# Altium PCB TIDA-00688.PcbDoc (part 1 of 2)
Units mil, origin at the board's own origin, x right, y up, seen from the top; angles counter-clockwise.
Board outline 1000 x 2450.32 mil, 4 copper layers (Top Layer, Signal Layer 1, Signal Layer 2, Bottom Layer), stack 61.6 mil thick; 78 components, 39 nets, 179 pads, 94 vias.
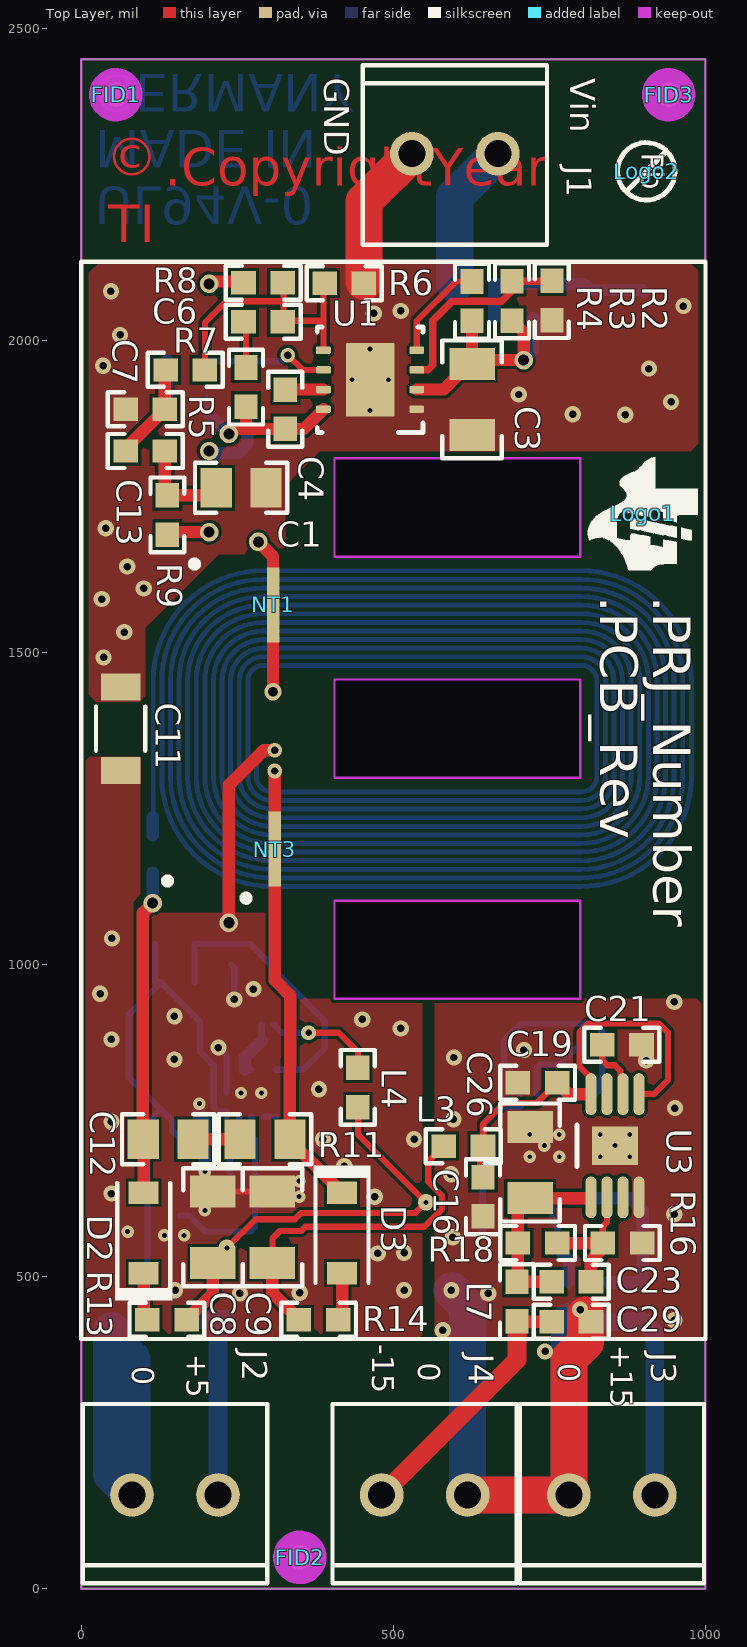
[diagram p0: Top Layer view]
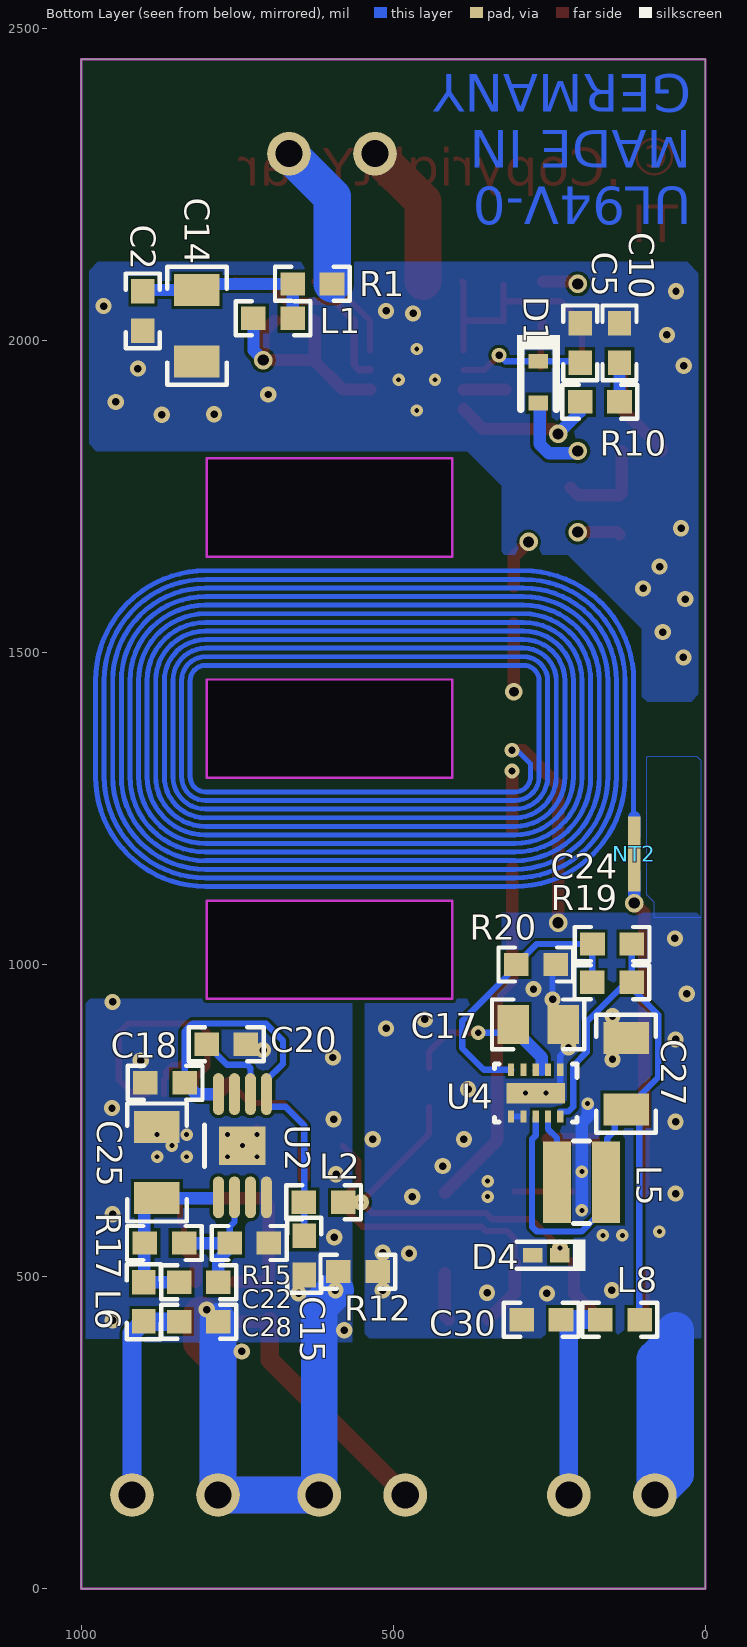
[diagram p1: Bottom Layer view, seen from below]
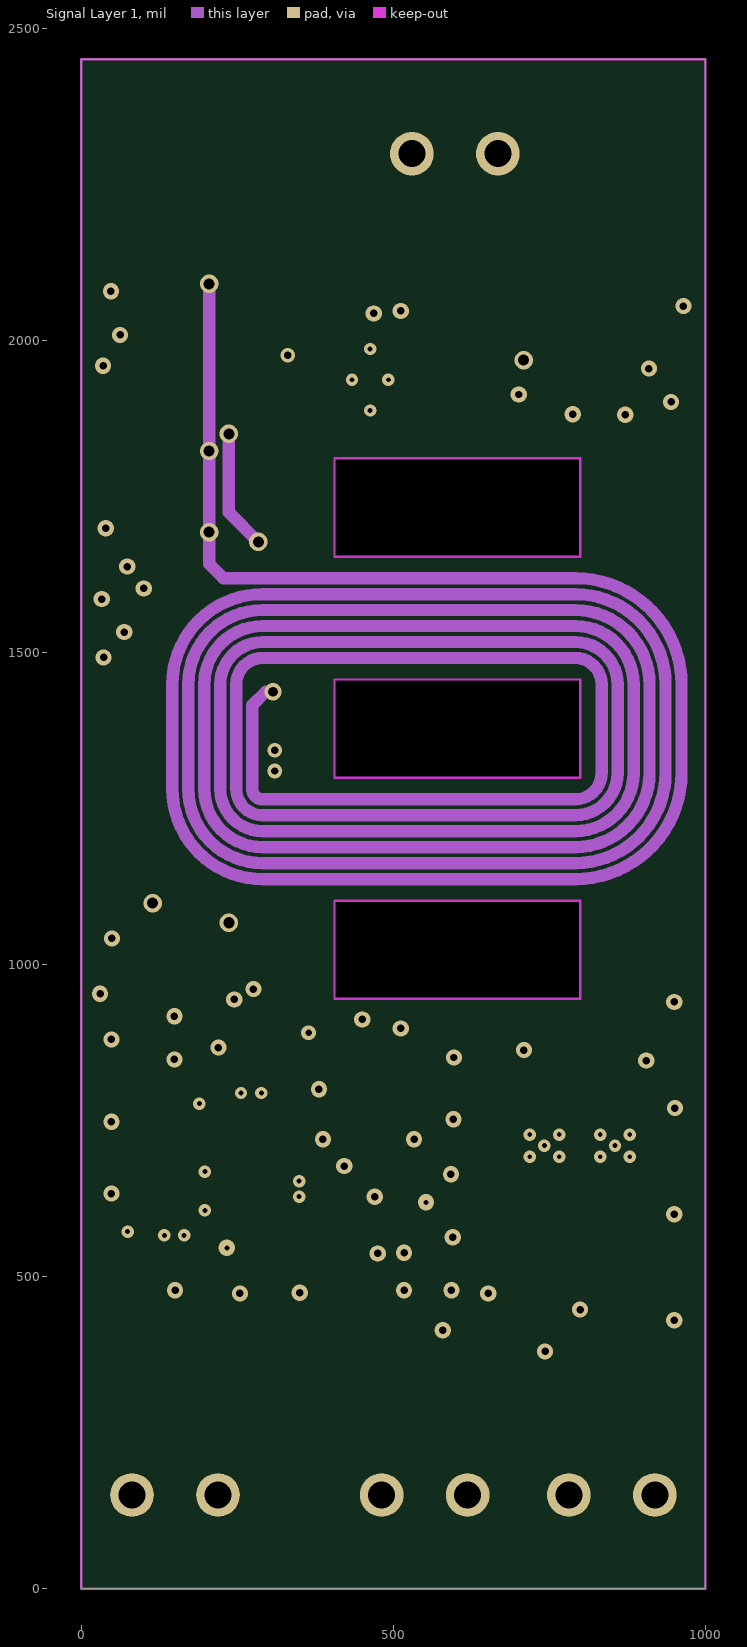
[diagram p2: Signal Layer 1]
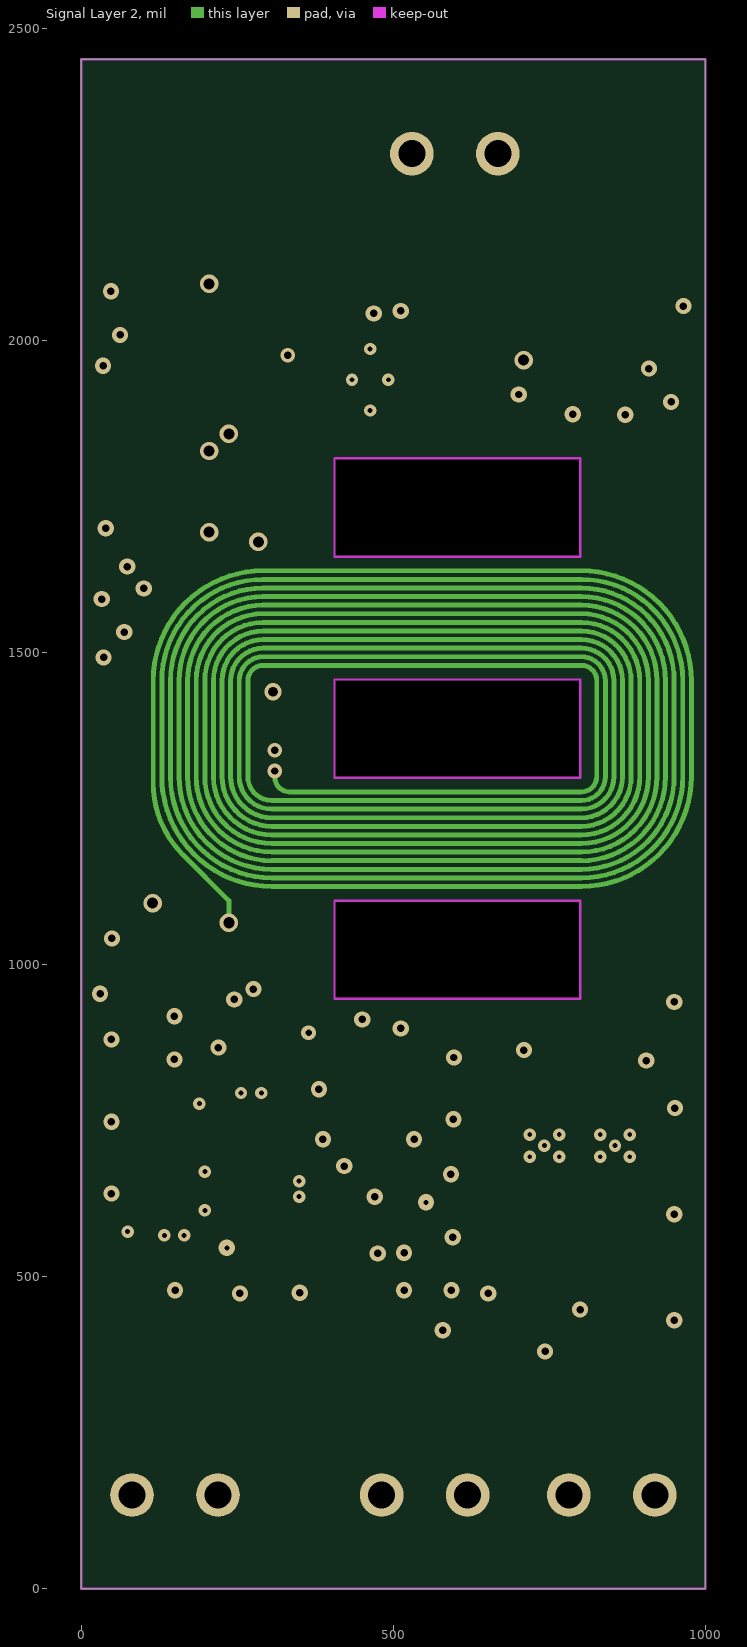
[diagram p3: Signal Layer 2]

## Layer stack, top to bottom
Top Solder: solder mask 0.4, Solder Resist, Dk 3.5
Top Layer: signal copper 1.4
Dielectric 1: core 8, Dk 4.2
Signal Layer 1: signal copper 1.4
Dielectric 2: prepreg 40, FR-4, Dk 4.2
Signal Layer 2: signal copper 1.4
Dielectric 3: core 8, Dk 4.2
Bottom Layer: signal copper 1.4
Bottom Solder: solder mask 0.4, Solder Resist, Dk 3.5

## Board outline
0,0 0,2450.32 1000,2450.32 1000,0
cut-out: 405.51,1102.36 405.51,944.88 799.21,944.88 799.21,1102.36
cut-out: 405.51,1811.02 405.51,1653.54 799.21,1653.54 799.21,1811.02
cut-out: 405.51,1456.69 405.51,1299.21 799.21,1299.21 799.21,1456.69

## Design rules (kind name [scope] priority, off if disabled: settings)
AssemblyTestPointUsage [All] p1 off:
AssemblyTestpoint [All] p1 off: testpointundercomponent=TRUE minsize=40 maxsize=100 preferedsize=60 minholesize=0 maxholesize=40 preferedholesize=32 testpointgrid=1 usegrid=TRUE gridtolerance=0.01 allowsidetop=TRUE allowsidebottom=TRUE
Clearance [All] p1: gap=4.92
ComponentClearance [All] p1: gap=0 collisioncheckmode=3 verticalgap=10 showdistances=FALSE
DiffPairsRouting [All] p1: maxlimit=393.7 minlimit=4.92 mostfreqgap=5.91 toplayer_minwidth=15 toplayer_maxwidth=15 toplayer_prefwidth=15 midlayer1_minwidth=15 midlayer1_maxwidth=15 midlayer1_prefwidth=15 midlayer2_minwidth=15 midlayer2_maxwidth=15 midlayer2_prefwidth=15 bottomlayer_minwidth=15 bottomlayer_maxwidth=15 bottomlayer_prefwidth=15 maxuncoupledlength=500
FabricationTestPointUsage FabricationTestPointUsage_1 [All] p1 off: valid=0 allowmultiple=FALSE
FabricationTestpoint FabricationTestpoint_1 [All] p1 off: side=3 testpointundercomponent=TRUE minsize=40 maxsize=100 preferedsize=60 minholesize=0 maxholesize=40 preferedholesize=32 testpointgrid=1 allowsidetop=TRUE allowsidebottom=TRUE usegrid=TRUE gridtolerance=0.01
HoleSize [All] p1: absolutevalues=TRUE maxlimit=236.22 minlimit=7.87 maxpercent=80.000 minpercent=20.000
HoleSize FabricationTestpoint [All] p2 off: absolutevalues=TRUE maxlimit=100 minlimit=1 maxpercent=80.000 minpercent=20.000
HoleSize FabricationTestPointUsage [All] p3 off: absolutevalues=TRUE maxlimit=100 minlimit=1 maxpercent=80.000 minpercent=20.000
MinimumSolderMaskSliver [All] p1 off: minsoldermaskwidth=10
PlaneClearance [All] p1: clearance=19.68
PlaneConnect [All] p1: planeconnectstyle=Relief reliefexpansion=15.75 reliefentries=4 reliefconductorwidth=5.91 reliefairgap=5.91
PolygonConnect [All] p1: connectstyle=Direct reliefconductorwidth=5.91 reliefentries=4 polygonreliefangle="90 Angle" airgapwidth=10
RoutingCorners [All] p1: cornerstyle=45-Degree minsetback=49.21 maxsetback=49.21
RoutingVias [All] p1: holewidth=11.81 width=23.62 viastyle="Through Hole" minholewidth=7.87 minwidth=17.72 maxholewidth=17.72 maxwidth=29.53
SilkToSilkClearance [All] p1 off: silktosilkclearance=10
SilkToSolderMaskClearance [IsPad] p1 off: minsilkscreentomaskgap=10 clearancetoexposedcopper=TRUE
SolderMaskExpansion [All] p1: expansion=2.95
UnpouredPolygon [All] p1: allowunpoured=FALSE
Width [All] p1: maxlimit=393.7 minlimit=4.92 preferedwidth=5.91
16 further rules are at their usual default settings.

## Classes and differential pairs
component class Logo: Logo1 Logo2
component class TIDA-00688_Hardware: FID1 FID2 FID3 Logo1 Logo2
component class FiducialMark: FID1 FID2 FID3
component class TIDA-00688_Schematics: C1 C2 C3 C4 C5 C6 C7 C8 C9 C10 C11 C12 C13 C14 C15 C16 C17 C18 C19 C20 C21 C22 C23 C24 C25 C26 C27 C28 C29 C30 D1 D2 D3 D4 J1 J2 J3 J4 L1 L2 L3 L4 L5 L6 L7 L8 NT1 NT2 NT3 R1 R2 R3 R4 R5 R6 R7 R8 R9 R10 R11 R12 R13 R14 R15 R16 R17 R18 R19 R20 U1 U2 U3 U4
component class Connectors: J1 J2 J3 J4

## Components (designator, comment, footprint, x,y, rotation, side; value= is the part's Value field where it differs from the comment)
C1 "GRM21BR71E155KA88L" 0805_HV 255.91,1763.78 r0 top
C2 "C1608X7R1H104K" 0603 901.57,2047.24 r270 bottom
C3 "UMK316B7225KD-T" 1206_033 625.98,1905.51 r270 top
C4 "C0603C103J5RACTU" 0603 326.77,1889.76 r270 top
C5 "GRM188R71E105KA12D" 0603 200.79,1996.06 r90 bottom
C6 "GCM188R71H104KA57D" 0603 291.27,2029.93 r0 top
C7 "GRM188R71H223KA01D" 0603 102.36,1889.76 r180 top
C8 "GRM31CR71E475KA88L" 1206 210.69,579 r90 top
C9 "GRM31CR71E475KA88L" 1206 306,579 r270 top
C10 "C0603C471K5RACTU" 0603 137.8,1996.06 r90 bottom
C11 "202R18W102KV4E" 1206_190 62.99,1377.95 r90 top
C12 "GRM21A5C2E560JW01D" 0805_HV 139,720 r180 top
C13 "GRM188R71H153KA01D" 0603 102.36,1822.83 r180 top
C14 "UMK316B7225KD-T" 1206_033 814.96,2023.62 r270 bottom
C15 "C0603C105K3RACTU" 0603 643,534 r270 bottom
C16 "C0603C105K3RACTU" 0603 643.5,627.86 r270 top
C17 "C2012X7R1V225K085AC" 0805_HV_033 268,904 r180 bottom
C18 "C1608X7R1H104K" 0603 866,810.7 r0 bottom
C19 "C1608X7R1H104K" 0603 731,810.7 r180 top
C20 "C0603C103J5RACTU" 0603 768,872 r0 bottom
C21 "C0603C103J5RACTU" 0603 866,871.7 r180 top
C22 "C0603C103J5RACTU" 0603 812,490.7 r0 bottom
C23 "C0603C103J5RACTU" 0603 785,491.7 r180 top
C24 "GRM188R71E102KA01D" 0603 149.61,1032.89 r0 bottom
C25 "C3216X7R1E475K085AB" 1206_033 879,682.7 r90 bottom
C26 "C3216X7R1E475K085AB" 1206_033 719,682.7 r90 top
C27 "C3216X7R1A106M085AC" 1206_033 127.13,825 r90 bottom
C28 "C1608X7R1H104K" 0603 812,427.7 r180 bottom
C29 "C1608X7R1H104K" 0603 785,427.7 r0 top
C30 "C1608X7R1H104K" 0603 263,431 r0 bottom
D1 "CDBU0245" SOD-523F 267.72,1933.07 r270 bottom
D2 "RF081M2STR" SOD-123 99.69,570 r90 top
D3 "RF081M2STR" SOD-123 417.6,570 r270 top
D4 "BZT52C24T-7" SOD-523 255,534 r0 bottom
FID1 "Fiducial" Fiducial10-20 55.12,2393.7 r0 top
FID2 "Fiducial" Fiducial10-20 350,50 r0 top
FID3 "Fiducial" Fiducial10-20 940.94,2393.7 r0 top
J1 "1751248" CONN_1751248 598.43,2299.21 r180 top
J2 "1751248" CONN_1751248 150,150 r0 top
J3 "1751248" CONN_1751248 850,150 r0 top
J4 "1751248" CONN_1751248 550,150 r0 top
L1 "LQM18PN2R2MFH" 0603 692.91,2035.43 r0 bottom
L2 "BLM18KG601SN1D" 0603 612,619 r0 bottom
L3 "BLM18KG601SN1D" 0603 612,709 r0 top
L4 "BLM18KG601SN1D" 0603 443,803 r90 top
L5 "VLS3010ET-220M" VLS3010 198.5,651 r180 bottom
L6 "BLM18KG601SN1D" 0603 900,459.7 r270 bottom
L7 "BLM18KG601SN1D" 0603 698,460 r270 top
L8 "BLM18KG601SN1D" 0603 137,431 r0 bottom
Logo1 "Texas Instruments" TI_Symbol_Overlay_Small 899.17,1722.12 r270 top
Logo2 "Pb-Free Symbol" Pb-Free_Overlay_Small 905.12,2271 r270 top
NT1 "Net-Tie" Net-Tie_20milWide_60milLong 307.13,1576.33 r270 top net-tie
NT2 "Net-Tie" Net-Tie_20milWide_60milLong 114.17,1177.17 r270 bottom net-tie
NT3 "Net-Tie" Net-Tie_20milWide_60milLong 309.94,1185.04 r270 top net-tie
R1 "CRCW06031R00FKEA" 0603 629.92,2090.55 r180 bottom
R2 "CRCW060316K9FKEA" 0603 689.9,2063.35 r270 top
R3 "CRCW06032K00FKEA" 0603 753.94,2063.98 r90 top
R4 "CRCW0603453KFKEA" 0603 625.98,2062.99 r90 top
R5 "CRCW060327K4FKEA" 0603 263.78,1925.2 r90 top
R6 "CRCW06032K00FKEA" 0603 421.17,2091.9 r180 top
R7 "CRCW060342R2FKEA" 0603 166.34,1952.76 r0 top
R8 "CRCW060311K8FKEA" 0603 291.27,2092.34 r180 top
R9 "ERJ-3GEY0R00V" 0603 137.8,1720.47 r270 top
R10 "CRCW06031R00FKEA" 0603 169.29,1901.57 r0 bottom
R11 "CRCW08051K00FKEA" 0805_HV 294,720 r0 top
R12 "CRCW06030000Z0EA" 0603 557,508 r0 bottom
R13 "ERJ-3GEY0R00V" 0603 137,431 r180 top
R14 "ERJ-3GEY0R00V" 0603 380,431 r0 top
R15 "CRCW06032K00FKEA" 0603 731,553.7 r0 bottom
R16 "CRCW06032K00FKEA" 0603 867,553.7 r180 top
R17 "CRCW060323K2FKEA" 0603 867,553.7 r0 bottom
R18 "CRCW060323K7FKEA" 0603 731,553.7 r180 top
R19 "CRCW060353K6FKEA" 0603 149.82,971.46 r180 bottom
R20 "CRCW060310K0FKEA" 0603 271.65,1000 r0 bottom
U1 "LM5017SDX/NOPB" NGU0008B 462.6,1937 r180 top
U2 "TPS7A4901DGN" DGN0008D_N 742,709.7 r90 bottom
U3 "TPS7A3001DGN" DGN0008D_N 855,709.7 r90 top
U4 "TPS62175DQCR" DQC0010A 272,794 r270 bottom

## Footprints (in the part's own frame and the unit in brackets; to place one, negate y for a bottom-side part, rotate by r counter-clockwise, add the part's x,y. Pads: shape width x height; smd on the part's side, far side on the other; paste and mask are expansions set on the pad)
0603 [mm] "0603 from SM-752 data"
  rect 1x0.95 smd: 1(-0.8,0) 2(0.8,0)
  silkscreen extent -1.52,-0.69 1.52,0.69, body extent -0.87,-0.47 0.87,0.47, height 1
0805_HV [mil] "0805 with 30mil clearance between pads"
  rect 50x63 smd: 1(-40,0) 2(40,0)
  silkscreen extent -74,-40 74,40, body extent -43,-29 43,29, height 57
0805_HV_033 [mil]
  rect 50x63 smd: 1(-40,0) 2(40,0)
  silkscreen extent -74,-40 74,40, body extent -43,-29 43,29, height 33
1206 [mm] "1206 from SM-752 data"
  rect 1.3x1.85 smd: 1(-1.45,0) 2(1.45,0)
  silkscreen extent -2.4,-1.21 2.4,1.21, body extent -1.7,-0.9 1.7,0.9, height 1.35
1206_033 [mm]
  rect 1.3x1.85 smd: 1(-1.45,0) 2(1.45,0)
  silkscreen extent -2.4,-1.21 2.4,1.21, body extent -1.7,-0.9 1.7,0.9, height 0.85
1206_190 [mm] "1206_190"
  rect 1.1x1.6 smd: 1(-1.7,0) 2(1.7,0)
  silkscreen extent -0.9,-1 0.9,1, body extent -1.75,-0.95 1.75,0.95, height 1.9
CONN_1751248 [mil] "Phoenix Contact"
  round 70 hole 43.31: 1(-68.9,0) 2(68.9,0)
  silkscreen extent -148,-142 148,146, body extent -148,-142 148,146, height 335
DGN0008D_N [mm]
  oval 1.7x0.45 smd: 1(-2.1,0.975) 2(-2.1,0.325) 3(-2.1,-0.325) 4(-2.1,-0.975) 5(2.1,-0.975) 6(2.1,-0.325) 7(2.1,0.325) 8(2.1,0.975)
  rect 1.57x1.89 smd: 9(0,0)
  silkscreen extent -0.85,1.55 0.85,1.55, body extent -2.45,-1.5 2.45,1.5, height 0.94
DQC0010A [mm] "SON, 10-Leads, Body 2x3mm, Pitch 0.5mm, Thermal Pad 2.4x0.84mm"
  rect 0.5x0.25 smd: 1(-0.95,1) 2(-0.95,0.5) 3(-0.95,0) 4(-0.95,-0.5) 5(-0.95,-1) 6(0.95,-1) 7(0.95,-0.5) 8(0.95,0) 9(0.95,0.5) 10(0.95,1)
  rect 0.84x2.4 smd paste-0.42: 11(0,0)
  silkscreen extent -1.17,-1.68 1.17,1.68, body extent -1.05,-1.55 1.05,1.55, height 0.81
Fiducial10-20 [mm]
  round 1 smd mask+0.5: 1(0,0)
  Top Layer keep-out circle w1.178: c0,0 r0.5
Net-Tie_20milWide_60milLong [mil] "20mil net tie, no solder mask opening, no solder paste"
  rect 60x20 smd paste-10 mask-10: 1(-30,0) 2(30,0)
NGU0008B [mm] "SON, 8-Leads, Body 4x4mm, Pitch 0.8mm"
  rrect33% 0.6x0.3 smd: 1(-1.9,1.2) 2(-1.9,0.4) 3(-1.9,-0.4) 4(-1.9,-1.2) 5(1.9,-1.2) 6(1.9,-0.4) 7(1.9,0.4) 8(1.9,1.2)
  rrect5% 1.98x3 smd paste-1.5: 9(0,0)
  silkscreen extent -2.15,-2.15 2.15,2.15, body extent -2.05,-2.05 2.05,2.05, height 0.81
Pb-Free_Overlay_Small [mil]
  silkscreen extent -46,-46 46,46
SOD-123 [mm] "On Semi recommended land pattern"
  rect 0.915x1.22 smd: 1(-1.637,0) 2(1.637,0)
  silkscreen extent -2.74,-1.17 2.03,1.17, body extent -1.93,-0.9 1.93,0.9, height 1.35
SOD-523 [mm] "NXP Semiconductor recommended land pattern, nominal STEP model"
  rect 0.8x0.6 smd paste-0.05: 1(-0.55,0) 2(0.55,0)
  silkscreen extent -1.6,-0.64 1.2,0.64, body extent -0.8,-0.4 0.8,0.4, height 0.72
SOD-523F [mm]
  rect 0.6x0.8 smd paste-0.05: 1(-0.85,0) 2(0.85,0)
  silkscreen extent -1.92,-0.87 1.1,0.87, body extent -0.9,-0.5 0.9,0.5, height 0.85
TI_Symbol_Overlay_Small [mil]
  silkscreen extent -90,-88 91,88
VLS3010 [mil]
  rect 45x130 smd: 1(-39.37,0) 2(39.37,0)
  silkscreen extent -13,-66 13,66, body extent -61,-61 61,61, height 39

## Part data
C1: "CAP, CERM, 1.5 µF, 25 V, +/- 10%, X7R, 0805"
C2 C6 C18 C19 C28 C29 C30: "CAP, CERM, 0.1 µF, 50 V, +/- 10%, X7R, 0603"
C3 C14: "CAP, CERM, 2.2 µF, 50 V, +/- 10%, X7R, 1206"
C4 C20 C21 C22 C23: "CAP, CERM, 0.01 µF, 50 V, +/- 5%, X7R, 0603"
C5 C15 C16: "CAP, CERM, 1 µF, 25 V, +/- 10%, X7R, 0603"
C7: "CAP, CERM, 0.022 µF, 50 V, +/- 10%, X7R, 0603"
C8 C9 C25 C26: "CAP, CERM, 4.7 µF, 25 V, +/- 10%, X7R, 1206"
C10: "CAP, CERM, 470 pF, 50 V, +/- 10%, X7R, 0603"
C11: "CAP, CERM, 1000 pF, 2000 V, +/- 10%, X7R, 1206_190"
C12: "CAP, CERM, 56 pF, 250 V, +/- 5%, C0G/NP0, 0805"
C13: "CAP, CERM, 0.015 µF, 50 V, +/- 10%, X7R, 0603"
C17: "CAP, CERM, 2.2 µF, 35 V, +/- 10%, X7R, 0805"
C24: "CAP, CERM, 1000 pF, 25 V, +/- 10%, X7R, 0603"
C27: "CAP, CERM, 10 µF, 10 V, +/- 20%, X7R, 1206"
D1: "Diode, Schottky, 45 V, 0.2 A, SOD-523F"
D2 D3: "Diode, Fast Rectifier, 200 V, 0.8 A, SOD-123"
D4: "Diode, Zener, 24 V, 300 mW, SOD-523"
FID1 FID2 FID3: "Fiducial mark.  There is nothing to buy or mount."
J1 J2 J3 J4: "Conn Term Block, 2POS, 3.5mm, TH"
L1: "Inductor, Ferrite, 2.2 µH, 0.35 A, 0.38 ohm, SMD"
L2 L3 L4 L6 L7 L8: "Ferrite Bead, 600 ohm @ 100 MHz, 1.3 A, 0603"
L5: "Inductor, Shielded, Ferrite, 22 µH, 0.38 A, 0.9 ohm, SMD"
Logo1: library part TI_Logo, "Texas Instrument Corporate Signature"
Logo2: library part Pb-Free
NT1 NT2 NT3: "Single point connection between nets."
R1 R10: "RES, 1.00, 1%, 0.1 W, 0603"
R2: "RES, 16.9 k, 1%, 0.1 W, 0603"
R3 R6 R15 R16: "RES, 2.00 k, 1%, 0.1 W, 0603"
R4: "RES, 453 k, 1%, 0.1 W, 0603"
R5: "RES, 27.4 k, 1%, 0.1 W, 0603"
R7: "RES, 42.2, 1%, 0.1 W, 0603"
R8: "RES, 11.8 k, 1%, 0.1 W, 0603"
R9 R12 R13 R14: "RES, 0, 5%, 0.1 W, 0603"
R11: "RES, 1.00 k, 1%, 0.125 W, 0805"
R17: "RES, 23.2 k, 1%, 0.1 W, 0603"
R18: "RES, 23.7 k, 1%, 0.1 W, 0603"
R19: "RES, 53.6 k, 1%, 0.1 W, 0603"
R20: "RES, 10.0 k, 1%, 0.1 W, 0603"
U1: "100V, 600mA Constant On-Time Synchronous Buck Regulator, NGU0008B"
U2: "+36V, +150mA, Ultralow-Noise, Positive LINEAR REGULATOR, DGN0008D"
U3: "-36V, -200mA, Ultralow-Noise, High PSRR, Adjustable -1.18 to -33 V Output, Negative Linear Regulator, 8-pin MSOP (DGN), -40 to 125 degC, Green (RoHS & no Sb/Br)"
U4: "28V, 0.5A Step-Down Converter with Sleep Mode, DQC0010A"

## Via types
v1: diameter 26, hole 12, Top Layer to Bottom Layer, tented both sides, 55 vias
v2: diameter 20, hole 7.87, Top Layer to Bottom Layer, 10 vias
v3: diameter 29.53, hole 17.72, Top Layer to Bottom Layer, 8 vias
v4: diameter 20, hole 8, Top Layer to Bottom Layer, tented both sides, 7 vias
v5: diameter 19.68, hole 7.87, Top Layer to Bottom Layer, 6 vias
v6: diameter 23.62, hole 11.81, Top Layer to Bottom Layer, 3 vias
v7: diameter 26, hole 8, Top Layer to Bottom Layer, tented both sides, 2 vias
v8: diameter 24, hole 10, Top Layer to Bottom Layer, 1 vias
v9: diameter 20, hole 8, Top Layer to Bottom Layer, 1 vias
v10: diameter 27.56, hole 15.75, Top Layer to Bottom Layer, 1 vias

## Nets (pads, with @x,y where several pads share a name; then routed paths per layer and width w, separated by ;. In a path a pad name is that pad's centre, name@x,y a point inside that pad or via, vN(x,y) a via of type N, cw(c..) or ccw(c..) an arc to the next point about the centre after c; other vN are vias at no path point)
GND: C1.2 C2.2 C3.2 C5.2 C7.2 C10.2 C11.2 C14.2 J1.2 R3.1 R6.1 U1.1 U1.9 | length 236.5
  Top Layer w59.06: R6.1@452.76,2094.49 452.76,2222.44 J1.2@529.53,2299.21
  other v1: 35.43,1492.13 68.58,1532.67 32.44,1585.62 100.02,1602.71 73.62,1637.73 39.16,1699.08 871.41,1880.82 787.4,1881.89 944.88,1901.57 700.79,1913.39 909.45,1954.87 34.77,1959.44 61.86,2008.76 468.5,2043.31 511.81,2047.24 964.57,2055.12 47.24,2078.74
  other v5: 462.6,1887.79 433.47,1937 491.73,1937 462.6,1986.22
GNDA: C15.2 C16.2 C18.2 C19.2 C20.1 C21.1 C25.2 C26.2 C28.2 C29.2 J3.1 J4.2 R12.2 R15.1 R16.1 U2.4 U2.9 U3.4 U3.9 | length 1320
  Top Layer w10: C26.2@719,739.79 719,732.7 v2(742,709.7)
  Top Layer w59.06: J4.2@618.9,150 J3.1@781.1,150 781.1,368.2 807.64,394.73 C29.2@807.64,438.55
  Bottom Layer w10: v2(855,709.7) 879,733.7 C25.2@879,739.79
  Bottom Layer w59.06: v1(593,478) 618.9,452.1 J4.2@618.9,150 J3.1@781.1,150 C28.2@781.1,427.7
  other v1: 743,380 579,414 950,430 799,447 652,473 595,563 950,600 592,664 596,752 951,770 905,846 597,851 709,863 950,940
  other v2: 718.38,691.98 765.62,691.98 831.38,691.98 878.62,691.98 718.38,727.42 765.62,727.42 831.38,727.42 878.62,727.42
GNDS: C8.2 C9.1 C11.1 C17.2 C27.2 C30.2 D4.2 J2.1 NT2.1 NT3.1 R12.1 R20.1 U4.1 U4.6 U4.7 U4.11 | length 48467.1
  Top Layer w10: C8.2@210.69,636.09 C9.1@306,636.09
  Top Layer w20: v3(236.22,1066.93) 236.22,1287.4 292.32,1343.5 v6(309.94,1343.5) ; NT3.1@309.94,1215.04 v6(309.94,1310.04)
  Signal Layer 2 w7.87: 115.06,1454.72 cw(c291.24,1454.72) 291.24,1630.91 801.18,1630.91 cw(c801.18,1454.72) 977.36,1454.72 ; 115.06,1454.73 115.06,1290.45 ccw(c276.64,1290.45) 162.38,1176.2 236.22,1102.36 v3(236.22,1066.93) ; 170.18,1454.72 cw(c291.24,1454.72) 291.24,1575.79 801.18,1575.79 cw(c801.18,1454.72) 922.24,1454.72 ; 170.17,1454.73 170.17,1301.18 ccw(c305.02,1301.18) 305.02,1166.34 801.18,1166.34 ccw(c801.18,1301.18) 936.02,1301.18 936.02,1454.73 ; 211.51,1454.72 cw(c291.24,1454.72) 291.24,1534.45 801.18,1534.45 cw(c801.18,1454.72) 880.91,1454.72 ; 211.51,1454.73 211.51,1301.18 ccw(c305.02,1301.18) 305.02,1207.68 801.18,1207.68 ccw(c801.18,1301.18) 894.68,1301.18 894.69,1454.73 ; 225.29,1454.72 cw(c291.24,1454.72) 291.24,1520.67 801.18,1520.67 cw(c801.18,1454.72) 867.13,1454.72 ; 225.29,1454.73 225.29,1301.18 ccw(c305.02,1301.18) 305.02,1221.46 801.18,1221.46 ccw(c801.18,1301.18) 880.91,1301.18 880.91,1454.73 ; 266.63,1454.72 cw(c291.24,1454.72) 291.24,1479.33 801.18,1479.33 cw(c801.18,1454.72) 825.79,1454.72 ; 266.63,1454.73 266.63,1301.18 ccw(c305.02,1301.18) 305.02,1262.8 801.18,1262.8 ccw(c801.18,1301.18) 839.57,1301.18 839.57,1454.73 ; 291.24,1548.23 ccw(c291.24,1454.72) 197.73,1454.72 197.73,1301.18 ccw(c305.02,1301.18) 305.02,1193.9 801.18,1193.9 ccw(c801.18,1301.18) 908.46,1301.18 908.46,1454.73 ; 291.34,1548.23 801.18,1548.23 cw(c801.18,1454.72) 894.68,1454.72 ; v6(309.94,1310.04) 309.94,1300.2 ccw(c333.56,1300.2) 333.56,1276.57 801.18,1276.57 ccw(c801.18,1301.18) 825.79,1301.18 825.79,1454.73 ; 839.57,1454.72 ccw(c801.18,1454.72) 801.18,1493.11 291.24,1493.11 ccw(c291.24,1454.72) 252.85,1454.72 252.85,1301.18 ccw(c305.02,1301.18) 305.02,1249.02 801.18,1249.02 ccw(c801.18,1301.18) 853.35,1301.18 853.35,1454.73 ; 853.35,1454.72 ccw(c801.18,1454.72) 801.18,1506.89 291.24,1506.89 ccw(c291.24,1454.72) 239.07,1454.72 239.07,1301.18 ccw(c305.02,1301.18) 305.02,1235.24 801.18,1235.24 ccw(c801.18,1301.18) 867.13,1301.18 867.13,1454.73 ; 908.46,1454.72 ccw(c801.18,1454.72) 801.18,1562.01 291.24,1562.01 ccw(c291.24,1454.72) 183.96,1454.72 183.95,1301.18 ccw(c305.02,1301.18) 305.02,1180.12 801.18,1180.12 ccw(c801.18,1301.18) 922.24,1301.18 922.24,1454.73 ; 936.02,1454.72 ccw(c801.18,1454.72) 801.18,1589.57 291.24,1589.57 ccw(c291.24,1454.72) 156.4,1454.72 156.4,1301.18 ccw(c305.02,1301.18) 305.02,1152.56 801.18,1152.56 ccw(c801.18,1301.18) 949.8,1301.18 949.8,1454.73 ; 949.8,1454.72 ccw(c801.18,1454.72) 801.18,1603.35 291.24,1603.35 ccw(c291.24,1454.72) 142.62,1454.72 142.62,1301.18 ccw(c305.02,1301.18) 305.02,1138.78 801.18,1138.78 ccw(c801.18,1301.18) 963.58,1301.18 963.58,1454.73 ; 963.58,1454.72 ccw(c801.18,1454.72) 801.18,1617.13 291.24,1617.13 ccw(c291.24,1454.72) 128.84,1454.72 128.84,1301.18 ccw(c305.02,1301.18) 305.02,1125 801.18,1125 ccw(c801.18,1301.18) 977.36,1301.18 977.36,1454.73
  Bottom Layer w7.87: NT2.1@115.06,1208.05 115.06,1454.73 ; 115.06,1454.72 cw(c291.24,1454.72) 291.24,1630.91 801.18,1630.91 cw(c801.18,1454.72) 977.36,1454.72 ; 170.18,1454.72 cw(c291.24,1454.72) 291.24,1575.79 801.18,1575.79 cw(c801.18,1454.72) 922.24,1454.72 ; 170.17,1454.73 170.17,1301.18 ccw(c305.02,1301.18) 305.02,1166.34 801.18,1166.34 ccw(c801.18,1301.18) 936.02,1301.18 936.02,1454.73 ; 211.51,1454.72 cw(c291.24,1454.72) 291.24,1534.45 801.18,1534.45 cw(c801.18,1454.72) 880.91,1454.72 ; 211.51,1454.73 211.51,1301.18 ccw(c305.02,1301.18) 305.02,1207.68 801.18,1207.68 ccw(c801.18,1301.18) 894.69,1301.18 894.69,1454.73 ; 225.29,1454.72 cw(c291.24,1454.72) 291.24,1520.67 801.18,1520.67 cw(c801.18,1454.72) 867.13,1454.72 ; 225.29,1454.73 225.29,1301.18 ccw(c305.02,1301.18) 305.02,1221.46 801.18,1221.46 ccw(c801.18,1301.18) 880.91,1301.18 880.91,1454.73 ; 266.63,1454.72 cw(c291.24,1454.72) 291.24,1479.33 801.18,1479.33 cw(c801.18,1454.72) 825.79,1454.72 ; 266.63,1454.73 266.63,1301.18 ccw(c305.02,1301.18) 305.02,1262.8 801.18,1262.8 ccw(c801.18,1301.18) 839.57,1301.18 839.57,1454.73 ; v6@302.06,1343.5 280.41,1321.85 280.41,1301.18 ccw(c305.02,1301.18) 305.02,1276.57 801.18,1276.57 ccw(c801.18,1301.18) 825.79,1301.18 825.79,1454.73 ; 839.57,1454.72 ccw(c801.18,1454.72) 801.18,1493.11 291.24,1493.11 ccw(c291.24,1454.72) 252.85,1454.72 252.85,1301.18 ccw(c305.02,1301.18) 305.02,1249.02 801.18,1249.02 ccw(c801.18,1301.18) 853.35,1301.18 853.35,1454.73 ; 853.35,1454.72 ccw(c801.18,1454.72) 801.18,1506.89 291.24,1506.89 ccw(c291.24,1454.72) 239.07,1454.72 239.07,1301.18 ccw(c305.02,1301.18) 305.02,1235.24 801.18,1235.24 ccw(c801.18,1301.18) 867.13,1301.18 867.13,1454.73 ; 894.69,1454.72 ccw(c801.18,1454.72) 801.18,1548.23 291.24,1548.23 ccw(c291.24,1454.72) 197.73,1454.72 197.73,1301.18 ccw(c305.02,1301.18) 305.02,1193.9 801.18,1193.9 ccw(c801.18,1301.18) 908.46,1301.18 908.46,1454.73 ; 908.46,1454.72 ccw(c801.18,1454.72) 801.18,1562.01 291.24,1562.01 ccw(c291.24,1454.72) 183.96,1454.72 183.95,1301.18 ccw(c305.02,1301.18) 305.02,1180.12 801.18,1180.12 ccw(c801.18,1301.18) 922.24,1301.18 922.24,1454.73 ; 936.02,1454.72 ccw(c801.18,1454.72) 801.18,1589.57 291.24,1589.57 ccw(c291.24,1454.72) 156.4,1454.72 156.4,1301.18 ccw(c305.02,1301.18) 305.02,1152.56 801.18,1152.56 ccw(c801.18,1301.18) 949.8,1301.18 949.8,1454.73 ; 949.8,1454.72 ccw(c801.18,1454.72) 801.18,1603.35 291.24,1603.35 ccw(c291.24,1454.72) 142.62,1454.72 142.62,1301.18 ccw(c305.02,1301.18) 305.02,1138.78 801.18,1138.78 ccw(c801.18,1301.18) 963.58,1301.18 963.58,1454.73 ; 963.58,1454.72 ccw(c801.18,1454.72) 801.18,1617.13 291.24,1617.13 ccw(c291.24,1454.72) 128.84,1454.72 128.84,1301.18 ccw(c305.02,1301.18) 305.02,1125 801.18,1125 ccw(c801.18,1301.18) 977.36,1301.18 977.36,1454.73
  Bottom Layer w10: v1(219.5,867) 232.63,853.87 U4.11@232.63,794 ; R20.1@240.16,1000 245,995.16 v1(245,944) ; U4.7@291.69,756.6 U4.6@311.37,756.6
  Bottom Layer w20: NT2.1@114.17,1207.17 NT2.1@114.17,1236.22 ; v4(189,777) 189,755.85 198,746.85 v4(198,668) v9(198,606)
  Bottom Layer w59.06: 48,414 48,400.83 ; 48,400.83 81.1,367.73 J2.1@81.1,150 48,183.1 48,400.83
  other v1: 254,473 350,474 150,478 517,478 475,537 517,538 470,628 48,633 421,677 387,720 533,720 48,748 380.5,800 149,848 48,880 511.81,897.64 450,912 149,917 29.97,953.06 275.59,960.63 48.95,1041.77
  other v4: 133,566 164.43,566 74,572 349,628 349,653
  other v5: 255.62,794 288.38,794
NetC1_1: C1.1 C13.1 R9.1 | length 155.5
  Top Layer w20: C13.1@133.86,1822.83 133.86,1755.91 R9.1@137.8,1751.97 204.09,1751.97 C1.1@215.91,1763.78
NetC2_1: C2.1 C14.1 L1.1 R1.1 | length 300.2
  Bottom Layer w19.68: L1.1@661.42,2035.43 R1.1@661.42,2090.55 805.12,2090.55 C14.1@814.96,2080.71 899.6,2080.71 C2.1@901.57,2078.74
NetC3_1: C3.1 L1.2 R2.2 R4.1 U1.2 | length 397.6
  Top Layer w19.68: U1.2@537.4,1921.26 580.7,1921.26 625.98,1966.54 R4.1@625.98,2031.5 ; C3.1@627.95,1968.5 v3(708.66,1968.5) 708.66,2013.1 R2.2@689.9,2031.86
  Bottom Layer w19.68: v3(708.66,1968.5) 724.41,1984.25 L1.2@724.41,2035.43
NetC4_1: C4.1 U1.7 | length 66.9
  Top Layer w19.68: C4.1@320.87,1921.26 U1.7@387.8,1921.26
NetC4_2: C4.2 NT1.1 R5.1 R10.2 U1.8 | length 542.7
  Top Layer w19.68: v3(236.22,1850.39) 244.09,1858.26 263.63,1858.26 356.3,1858.26 U1.8@387.8,1889.76 ; 263.78,1858.42 R5.1@263.78,1893.7 ; v3(283.46,1677.17) 283.85,1677.17 307.09,1653.93 307.09,1606.37 NT1.1@307.13,1606.33
  Signal Layer 1 w19.68: v3(236.22,1850.39) 236.22,1724.41 v3(283.46,1677.17)
  Bottom Layer w19.68: R10.2@200.79,1901.57 200.79,1885.83 v3(236.22,1850.39)
NetC5_1: C5.1 D1.1 U1.6 | length 201.7
  Top Layer w10: v6(330.71,1976.38) 354.34,1952.75 U1.6@387.8,1952.75
  Bottom Layer w10: C5.1@200.79,1964.57 202.76,1966.54 259.84,1966.54 320.87,1966.54 v6(330.71,1976.38)
NetC6_1: C6.1 R5.2 | length 74.9
  Top Layer w10: C6.1@259.77,2029.93 263.78,2025.92 R5.2@263.78,1956.69
NetC6_2: C6.2 R6.2 R7.2 R8.1 U1.5 | length 449.1
  Top Layer w10: R7.2@197.84,1952.76 197.84,2028.54 232.28,2062.99 323.82,2062.99 ; C6.2@322.83,2031.5 387.8,2031.5 ; C6.2@323.82,2032.48 323.82,2062.99 ; R8.1@323.82,2089.57 323.82,2062.99 ; U1.5@387.8,1984.25 387.8,2031.5 ; R6.2@389.76,2094.49 387.8,2092.52 387.8,2031.5
NetC7_1: C7.1 C13.2 R7.1 | length 156.4
  Top Layer w20: C13.2@70.87,1822.83 70.87,1826.77 C7.1@133.86,1889.76 133.86,1951.77 R7.1@134.84,1952.76
NetC8_1: C8.1 D4.1 L2.1 L4.1 R13.1 | length 655.3
  Top Layer w10: v7(233,546) 279,592 342.13,592 352.13,602 535.02,602 v7(552.02,619) 443,728.02 L4.1@443,771.5
  Top Layer w20: R13.1@168.5,431 210.69,473.19 C8.1@210.69,521.91
NetC9_2: C9.2 L3.1 R14.1 | length 559.2
  Top Layer w10: C9.2@306,521.91 306,561 318,573 352,573 358.75,579.75 549.36,579.75 577.89,608.28 577.89,629.72 555.82,651.79 555.82,684.32 L3.1@580.5,709
  Top Layer w20: C9.2@306,521.91 306,473.5 R14.1@348.5,431
NetC10_1: C10.1 R10.1 | length 70.9
  Bottom Layer w19.68: R10.1@133.86,1901.58 R10.1@137.8,1901.57 C10.1@137.8,1968.5
NetC12_1: C12.1 R11.1 | length 76.8
  Top Layer w10: R11.1@253,720 254,721 R11.1@253,720
  Top Layer w20: C12.1@179,720 R11.1@253,720
NetC12_2: C12.2 D2.2 NT2.2 | length 522.3
  Top Layer w10: D2.2@97.89,636.26 D2.2@99.69,634.47 ; C12.2@99,720 C12.2@99.69,719.32
  Top Layer w20: C12.2@99,720 98.43,720.57 98.43,1082.68 v3(114.17,1098.43) ; D2.2@99.69,634.47 C12.2@99.69,719.32
  Bottom Layer w20: v3(114.17,1098.43) NT2.2@114.17,1147.17
NetC15_1: C15.1 C18.1 L2.2 U2.5 U2.8 | length 662.4
  Bottom Layer w10: C15.1@643,565.5 643,742 673,772 U2.5@704,772 ; U2.5@703.61,792.38 703.61,814.39 677,841 677,878 704.5,905.5 821.69,905.5 823.61,903.58 824.51,903.58 832.06,896.03 832.06,895.13 834.5,892.68 C18.1@834.5,810.7
  Bottom Layer w20: U2.8@783,792.38 816.18,792.38 C18.1@834.5,810.7
NetC16_1: C16.1 C19.1 L3.2 U3.5 U3.8 | length 718
  Top Layer w10: C19.1@762.5,810.7 730.05,778.25 677.25,778.25 644,745 ; U3.8@816.61,792.38 816.61,818.07 798,836.69 798,891.79 811.61,905.4 925.6,905.4 940,891 940,815 917.38,792.38 U3.5@893.39,792.38 ; 644,745 644,709 644,745
  Top Layer w20: C16.1@643.5,659.35 L3.2@643.5,709 ; C19.1@762.5,810.7 780.82,792.38 U3.8@812.87,792.38
NetC17_1: C17.1 L4.2 U4.2 U4.3 | length 272.7
  Top Layer w10: v8(364.12,890.65) 412.5,890.65 443,860.15 L4.2@443,834.5
  Bottom Layer w10: 262,831.4 U4.3@272,831.4 ; C17.1@289.13,878.03 C17.1@289.13,904 ; C17.1@308,904 321.35,890.65 v8(364.12,890.65)
  Bottom Layer w20: 262,831.4 262,850.91 C17.1@289.13,878.03
NetC20_2: C20.2 U2.6 | length 127.8
  Bottom Layer w10: U2.6@729.2,792.38 729.21,834.21 734.24,839.24 766.74,839.24 C20.2@799.5,872
NetC21_2: C21.2 U3.6 | length 100.1
  Top Layer w10: C21.2@834.5,871.7 834.5,846.5 842.28,838.72 854.27,838.72 863.94,829.05 863.94,819.06 867.8,815.21 U3.6@867.8,792.38
NetC22_1: C22.1 R15.2 R17.1 U2.2 | length 220
  Bottom Layer w10: U2.2@754.8,627.02 754.8,587.21 762.5,579.5 R15.2@762.5,553.7
  Bottom Layer w20: C22.1@780.5,490.7 780.5,527.5 762.5,545.5 R15.2@762.5,553.7 R17.1@835.5,553.7
NetC22_2: C22.2 C25.1 L6.1 R17.2 U2.1 | length 411
  Bottom Layer w20: U2.1@781.8,625.61 C25.1@879,625.61 C25.1@899.5,605.11 ; C22.2@843.5,490.7 L6.1@899.5,490.7 ; L6.1@899.5,490.7 899.5,553.7 C25.1@899.5,605.11 ; L6.1@899.5,490.7 C25.1@899.5,605.11
NetC23_1: C23.1 R16.2 R18.1 U3.2 | length 219
  Top Layer w10: R16.2@835.5,553.7 835.5,580.21 842.21,586.91 U3.2@842.2,627.02
  Top Layer w20: R18.1@762.5,553.7 R16.2@835.5,553.7 835.5,545.5 816.5,526.5 C23.1@816.5,491.7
